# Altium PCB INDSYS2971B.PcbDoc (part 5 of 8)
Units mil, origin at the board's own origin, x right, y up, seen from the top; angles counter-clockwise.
Board outline 6450 x 5820 mil, 6 copper layers (Top Layer, Int1 (PGND), Int2 (AGND), Int3 (Signal), Int4 (PGND), Bottom Layer), stack 70.536 mil thick; 787 components, 431 nets, 2530 pads, 2497 vias.
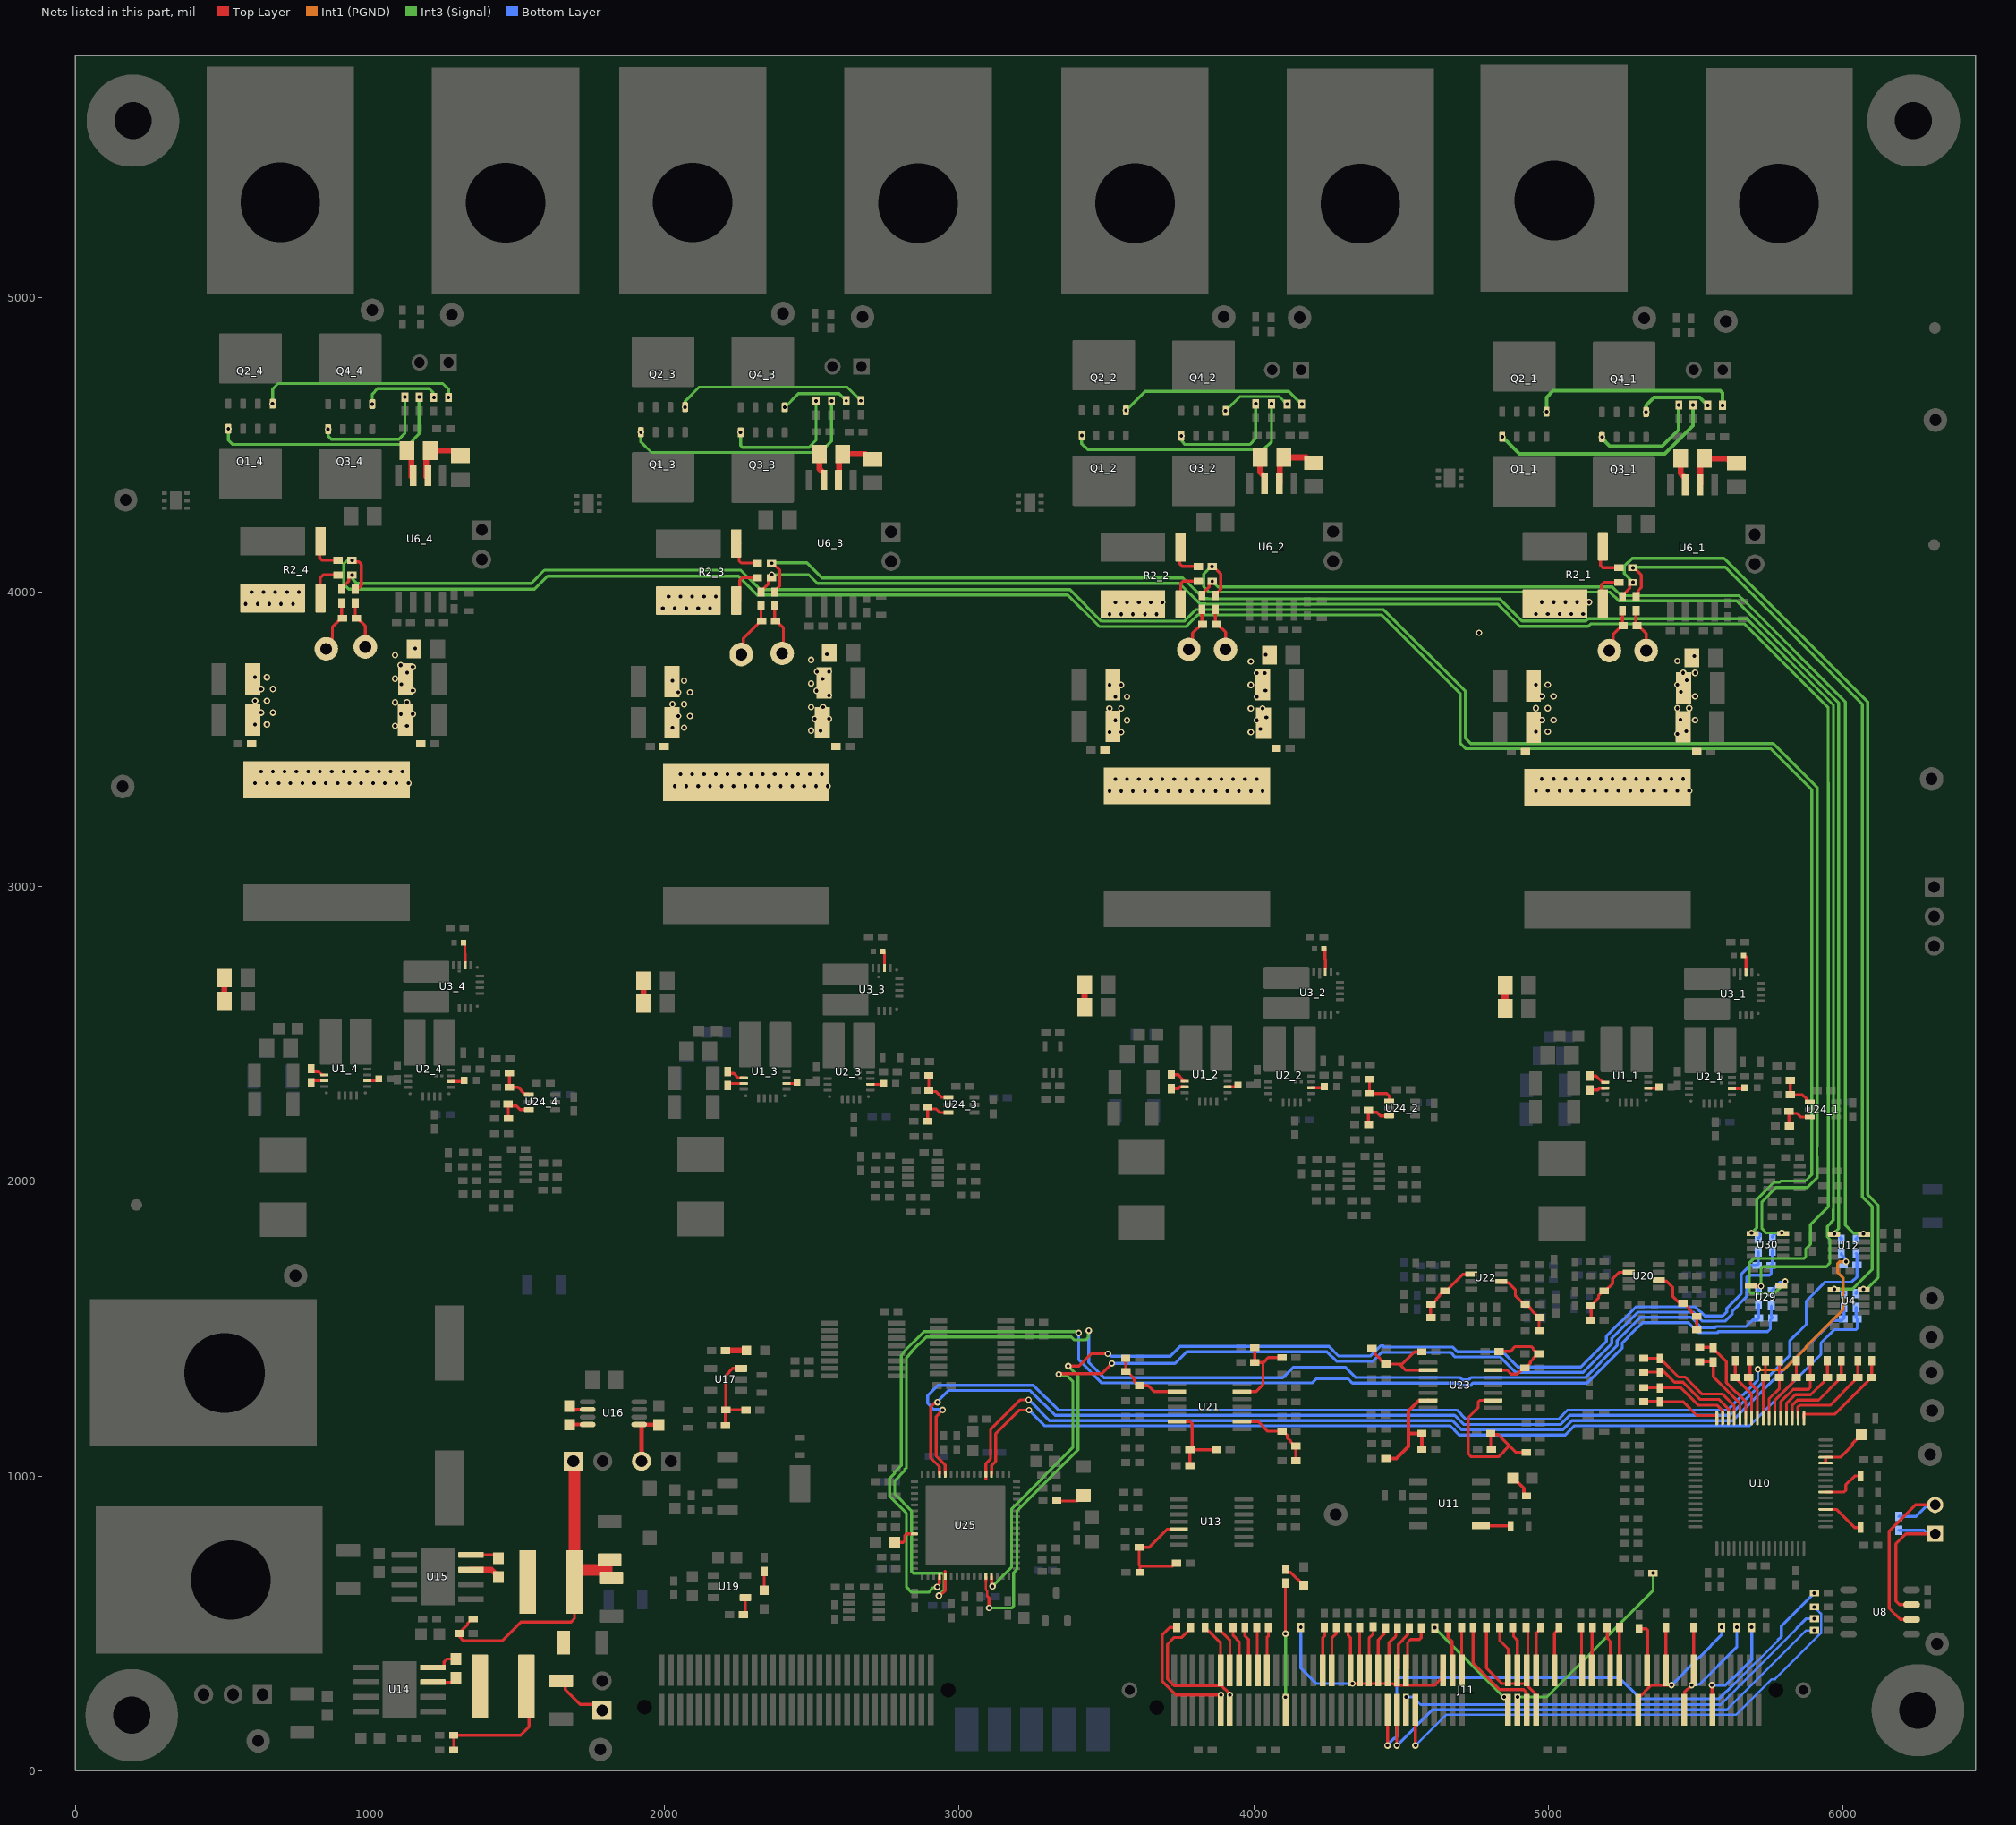
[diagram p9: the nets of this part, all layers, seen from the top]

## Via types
v1: diameter 22, hole 12.5, Top Layer to Bottom Layer, 873 vias
v2: diameter 22, hole 12, Top Layer to Bottom Layer, tented both sides, 788 vias
v3: diameter 22, hole 12, Top Layer to Bottom Layer, 586 vias
v4: diameter 22, hole 12.5, Top Layer to Bottom Layer, tented both sides, 249 vias
v5: diameter 24, hole 12, Top Layer to Bottom Layer, tented both sides, 1 vias

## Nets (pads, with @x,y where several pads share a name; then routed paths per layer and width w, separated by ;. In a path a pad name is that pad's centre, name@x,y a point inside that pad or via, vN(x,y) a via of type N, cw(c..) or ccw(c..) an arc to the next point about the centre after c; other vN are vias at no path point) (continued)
ISENA1: R4_1.1 R12_1.1 R210.1 U4.8 | length 3236.1
  Top Layer w10: R12_1.1@5252.12,3984.77 5252.12,3988.7 5276.41,4012.99 5276.41,4026.03 R4_1.1@5283.22,4032.84
  Int3 (Signal) w10: v2(5288.18,4033.35) 5258.39,4063.14 5258.39,4088.54 5285,4115.14 5596.3,4115.14 6084.34,3627.1 6084.34,1954.97 6117.15,1922.16 6120,1919.31 6120,1673.02 6083.45,1636.47 6072.3,1636.47 v2(6070,1634.17)
  Bottom Layer w10: R210.1@6045,1619.2 6045,1623.14 6051.81,1629.95 6062.53,1629.95 6066.75,1634.17 v2(6070,1634.17)
ISENA2: R4_2.1 R12_2.1 R211.1 U12.8 | length 4255
  Top Layer w10: R12_2.1@3824.12,3988.77 3824.12,3992.7 3848.41,4016.99 R4_2.1@3848.41,4030.03
  Int3 (Signal) w10: v2(3859.16,4036.84) 3859.32,4036.84 3878.14,4018.02 5217.13,4018.02 5247.13,3988.02 5647.4,3988.02 5665.28,3970.14 5666,3970.14 6008.59,3627.55 6008.59,1851.98 6036.18,1824.39 6067.7,1824.39 v2(6070,1822.09)
  Bottom Layer w10: R211.1@6045,1802.69 6045,1806.63 6058.17,1819.8 6067.7,1819.8 v2(6070,1822.09)
ISENA3: R4_3.1 R12_3.1 R212.1 U29.8 | length 6281.2
  Top Layer w10: R12_3.1@2327.51,4004.31 2351.8,4028.6 2351.8,4041.64 2358.61,4048.45 R4_3.1@2362.55,4048.45 2362.55,4058.64 v2(2363.38,4059.48) ; U29.8@5791.06,1644.83 5800.36,1644.83 5804.21,1648.69 v2(5804.21,1660.17)
  Int3 (Signal) w10: v2(2363.38,4059.48) 2489.37,4059.48 2518.71,4030.14 3747.54,4030.14 3817.54,3960.14 3837.44,3960.14 3838.19,3959.4 4828.48,3959.4 4903.48,3884.4 5135.68,3884.4 5143.56,3892.27 5667.32,3892.27 5950,3609.59 5950,3353.53 5950.43,3353.1 5950.43,2102.7 5950,2102.27 ; v2(5804.21,1660.17) 5804.21,1656.92 5798.21,1650.92 5798.21,1649.49 5768.91,1620.18 5687.52,1620.18 5681.66,1626.04 5681.66,1721.84 5698.37,1738.56 5868.49,1738.56 5874.35,1744.42 5874.35,1771.05 5890.23,1786.93 5890.23,1853.25 5950.43,1913.45 5950.43,2102.27
  Bottom Layer w10: R212.1@5757.14,1624.99 5757.14,1628.92 5786.09,1657.87 5801.92,1657.87 v2(5804.21,1660.17)
ISENA4: R4_4.1 R12_4.1 R213.1 U30.8 | length 7258.4
  Top Layer w10: R12_4.1@903.5,4009.77 903.5,4013.7 927.79,4037.99 927.79,4051.03 934.6,4057.84 v2(938.54,4057.84)
  Int3 (Signal) w10: v2(938.54,4057.84) 940.83,4055.55 940.83,4043.9 954.59,4030.14 1547.56,4030.14 1592.04,4074.62 2258.55,4074.62 2324.77,4008.41 3375.87,4008.41 3483.01,3901.27 3763.2,3901.27 3802.59,3940.66 4441.32,3940.66 4718.55,3663.44 4718.55,3504.12 4736.45,3486.22 5763.93,3486.22 5912.68,3337.46 5912.68,2118.34 5912.25,2117.91 5912.25,2086.64 5912.68,2086.21 5912.68,2012.27 5879.21,1978.8 5773.14,1978.8 5725.49,1931.14 5725.49,1839.34 5740,1824.83 v2(5792.78,1824.83)
  Bottom Layer w10: R213.1@5761.02,1810.42 5761.02,1814.12 5767.84,1820.93 5771.77,1820.93 5773.38,1822.53 5790.49,1822.53 v2(5792.78,1824.83)
ISENB1: R5_1.1 R13_1.1 R214.1 U4.1 | length 3221.9
  Top Layer w10: v2(5287.16,4082.84) 5291.1,4082.84 5315.78,4058.16 5315.78,4015.7 5304.81,4004.73 5304.81,3991.58 R13_1.1@5298,3984.77
  Int3 (Signal) w10: v2(5287.16,4082.84) 5288.45,4084.14 5602.03,4084.14 6066.47,3619.69 6066.47,1947.57 6099.28,1914.76 6099.28,1701.03 6032.42,1634.17 v2(5970.94,1634.17)
  Bottom Layer w10: v2(5970.94,1634.17) 5988.34,1634.17 5992.82,1629.69 5997.33,1629.69 6004.14,1622.88 R214.1@6004.14,1618.95
ISENB2: R5_2.1 R13_2.1 R215.1 U12.1 | length 4364.4
  Top Layer w10: v2(3858.08,4086.76) 3863.18,4086.76 3887.78,4062.16 3887.78,4010.48 3870,3992.7 R13_2.1@3870,3988.77
  Int3 (Signal) w10: v2(3858.08,4086.76) 3854.83,4086.76 3830,4061.92 3830,4018.14 3848,4000.14 5209.72,4000.14 5239.72,3970.14 5640,3970.14 5986.18,3623.97 5986.18,1840.13 5971.27,1825.22 v2(5971.27,1822.09)
  Bottom Layer w10: v2(5971.27,1822.09) 5973.56,1819.8 5981.83,1819.8 5995,1806.63 R215.1@5995,1802.69
ISENB3: R5_3.1 R13_3.1 R216.1 U29.1 | length 6188.8
  Top Layer w10: v2(2364.17,4098.25) 2366.69,4098.25 2391.17,4073.77 2391.17,4022.09 2373.39,4004.31 R13_3.1@2373.39,4000.37 ; U29.1@5688.7,1644.83 5689.08,1644.44 5721.43,1644.44 v2(5721.82,1644.06)
  Int3 (Signal) w10: v2(2364.17,4098.25) 2365.66,4099.74 2483.66,4099.74 2534.95,4048.45 3759.69,4048.45 3830.13,3978.02 3844.85,3978.02 3845.6,3977.27 4835.88,3977.27 4910.88,3902.27 5128.28,3902.27 5136.15,3910.14 5674.72,3910.14 5968.3,3616.56 5968.3,1906.05 5967.87,1905.62 5967.87,1867.74 5947.55,1847.42 5947.55,1832.14 5947.39,1831.98 5947.39,1811.81 5955.86,1803.35 5955.86,1722.16 5944.1,1710.4 5728.31,1710.4 5722.45,1704.54 5722.45,1644.69 v2(5721.82,1644.06)
  Bottom Layer w10: R216.1@5714.16,1629.2 5714.16,1633.15 5719.52,1638.52 5719.52,1641.76 v2(5721.82,1644.06)
ISENB4: R5_4.1 R13_4.1 R218.1 U30.1 | length 7383
  Top Layer w10: R5_4.1@942.47,4107.84 v2(938.54,4107.84) 943.89,4102.49 961.96,4102.49 969.77,4094.68 969.77,4021.54 958,4009.77 R13_4.1@949.38,4009.77 ; v2(5690,1824.83) 5692.14,1822.69 U30.1@5694.45,1822.69
  Int3 (Signal) w10: v2(938.54,4107.84) 938.07,4107.38 922.23,4107.38 909.77,4094.91 909.77,4027.87 927.5,4010.14 1558.54,4010.14 1602.42,4054.02 2251.22,4054.02 2314.7,3990.53 3368.47,3990.53 3475.6,3883.4 3770.6,3883.4 3809.99,3922.79 4433.92,3922.79 4700.68,3656.03 4700.68,3488.17 4720.51,3468.34 5756.52,3468.34 5894.81,3330.06 5894.81,2125.74 5894.38,2125.31 5894.38,2079.23 5894.81,2078.8 5894.81,2023.45 5872.61,2001.25 5789.46,2001.25 5784.87,1996.67 5765.74,1996.67 5707.61,1938.55 5707.61,1842.44 v2(5690,1824.83)
  Bottom Layer w10: v2(5690,1824.83) 5692.3,1822.53 5713.21,1822.53 5714.82,1820.93 5718.76,1820.93 5718.76,1813.53 R218.1@5713.15,1807.93
ISN1: C26.1 R214.2 U25.53 | length 3348.1
  Top Layer w10: 3090.43,990.14 U25.53@3090.43,1006.16 3090.43,1041.77 3106.3,1057.64 3106.3,1156.86 3208.07,1258.62 v2(3235.84,1258.62)
  Bottom Layer w10: v2(3235.84,1258.62) 3306.45,1188.02 4674.17,1188.02 4674.91,1187.28 4675.28,1187.28 4705.23,1157.33 5050.12,1157.33 5080.8,1188.02 5625.65,1188.02 5870.21,1432.58 5870.21,1432.72 5889.71,1452.21 5891.26,1452.21 5967.16,1528.11 5996.64,1528.11 6004.14,1535.61 R214.2@6004.14,1571.7
ISN2: C131.1 R215.2 U25.60 | length 3904.1
  Top Layer w10: v2(2943.76,1224.02) 2943.76,1223.77 2921.97,1201.97 2921.97,1068.41 2952.64,1037.74 U25.60@2952.64,1006.16
  Int1 (PGND) w10: v2(5711.7,1362.41) 5713.96,1360.14 5799.19,1360.14 5874.72,1435.67 5874.72,1438.64 6000.93,1564.85 6000.93,1672.79 5982.78,1690.94 5982.78,1721.39 5988.64,1727.25 v2(6010.77,1727.25)
  Bottom Layer w10: v2(2943.76,1224.02) 2941.47,1226.31 2913.5,1226.31 2892.77,1247.05 2892.77,1272.91 2927.87,1308.02 3252.13,1308.02 3336.38,1223.77 4689.35,1223.77 4720.04,1193.08 5035.31,1193.08 5066,1223.77 5608.96,1223.77 5711.7,1326.51 v2(5711.7,1362.41) ; R215.2@5995,1755.45 5995,1751.51 6008.48,1738.03 6008.48,1729.55 v2(6010.77,1727.25)
ISN3: C10.1 R216.2 U25.21 | length 4335.7
  Top Layer w10: v2(2931.36,593.7) 2934.61,593.7 2944.67,603.77 2946.54,603.77 2952.64,609.87 U25.21@2952.64,659.7 2952.64,676.14
  Int3 (Signal) w10: v2(2931.36,593.7) 2931.36,595.34 2949.07,613.05 2949.07,663.6 2942.39,670.27 2844.38,670.27 2838.52,676.13 2838.52,881.59 2781.75,938.37 2781.75,984.57 2814.65,1017.47 2814.65,1022.17 2821.12,1028.63 2821.12,1402.15 2837.14,1418.17 2837.14,1421.47 2887.94,1472.27 3380.57,1472.27 3391.11,1461.73 3429.61,1461.73 3437.7,1469.83 3437.7,1491.07 v2(3440,1493.36)
  Bottom Layer w10: v2(3440,1493.36) 3440,1385.42 3491.67,1333.75 4098.47,1333.75 4133.73,1369.02 4311.46,1369.02 4346.29,1334.19 4701.25,1334.19 4709.55,1325.89 4729.33,1325.89 4737.63,1334.19 5125.43,1334.19 5233.55,1442.31 5233.55,1459.56 5312.52,1538.53 5485.28,1538.53 5519.77,1504.04 5566.45,1504.04 5570.05,1507.64 5672.05,1507.64 5694.34,1529.93 5707.95,1529.93 C10.1@5714.76,1536.74 ; C10.1@5714.16,1541.69 R216.2@5714.16,1581.96
ISN4: C132.1 R218.2 U25.28 | length 3821.2
  Top Layer w8: 3090.43,644.78 3090.43,613.92 3095.43,608.92 3095.43,592.99
  Top Layer w10: 3090.43,644.78 U25.28@3090.43,659.7 ; 3095.43,592.99 3101.43,586.99 v2(3101.43,551.89) ; v2(3370,1373.17) 3406.34,1373.17 3447.91,1414.74 v2(3505,1414.74)
  Int3 (Signal) w10: v2(3101.43,551.89) 3178.19,551.89 3184.57,558.28 3184.57,671.56 3196.06,683.05 3196.06,880.82 3403.71,1088.47 3403.71,1339.45 v2(3370,1373.17)
  Bottom Layer w10: v2(3505,1414.74) 3508.25,1414.74 3516.6,1406.39 3716.7,1406.39 3750.21,1439.9 4255.52,1439.9 4288.26,1407.15 4396.05,1407.15 4430.82,1441.93 4439.11,1441.93 4443.51,1437.52 4676.02,1437.52 4691.52,1422.02 4844.85,1422.02 4896.93,1369.94 5110.63,1369.94 5197.8,1457.12 5197.8,1474.37 5297.71,1574.28 5500.09,1574.28 5530.98,1543.39 5592.62,1543.39 5606.23,1557 5606.23,1569.21 5655.15,1618.13 5655.15,1684.9 5685.07,1714.81 5708.53,1714.81 5713.15,1719.43 R218.2@5713.15,1760.68
ISP1: C26.2 R210.2 U25.52 | length 3381.7
  Top Layer w10: U25.52@3110.12,1006.16 3110.12,1036.18 3124.18,1050.24 3124.18,1143.2 3204.74,1223.76 v2(3236.94,1223.76) v2@3238.56,1223.76
  Bottom Layer w10: v2(3236.94,1223.76) 3290.56,1170.14 4666.55,1170.14 4667.29,1169.41 4667.87,1169.41 4681.86,1155.42 4681.86,1154.83 4697.24,1139.46 5057.52,1139.46 5088.21,1170.14 5682.7,1170.14 5925.75,1413.19 5925.75,1451.44 5971.1,1496.78 6043.08,1496.78 6048.94,1502.64 C26.2@6048.94,1533.16 6045,1537.1 R210.2@6045,1571.96
ISP2: C131.2 R211.2 U25.61 | length 3821.1
  Top Layer w10: v2(2926.51,1250.19) 2923.27,1250.19 2920.13,1247.05 2915.98,1247.05 2904.09,1235.17 2904.09,1061.01 2932.95,1032.15 U25.61@2932.95,1006.16
  Bottom Layer w10: v2(2926.51,1250.19) 2926.51,1253.44 2963.22,1290.14 3241.57,1290.14 3325.82,1205.89 4681.95,1205.89 4712.63,1175.21 5042.71,1175.21 5073.4,1205.89 5616.36,1205.89 5820.39,1409.93 5820.39,1459.07 5875.59,1514.27 5875.59,1593.94 5939.69,1658.05 6030.43,1658.05 6048.17,1675.79 C131.2@6048.17,1716.19 6048.17,1752.27 R211.2@6045,1755.45
ISP3: C10.2 R212.2 U25.20 | length 4314.6
  Top Layer w10: v2(2925.19,622.93) 2925.19,626.18 2932.95,633.94 U25.20@2932.95,659.7
  Int3 (Signal) w10: v2(2925.19,622.93) 2922.9,620.64 2911.56,620.64 2896.06,605.15 2839.14,605.15 2820.65,623.64 2820.65,874.19 2763.87,930.96 2763.87,991.98 2780.72,1008.82 2780.72,1013.51 2803.24,1036.04 2803.24,1409.55 2811.8,1418.11 2811.8,1421.41 2880.54,1490.14 3393.98,1490.14 3396.23,1487.9 3403.55,1487.9 v2(3405.84,1485.61)
  Bottom Layer w10: v2(3405.84,1485.61) 3405.84,1394.3 3484.27,1315.88 4198.3,1315.88 4212.57,1330.14 4320.17,1330.14 4335.3,1315.02 4695.15,1315.02 4702.15,1308.02 4736.73,1308.02 4743.73,1315.02 5131.54,1315.02 5251.43,1434.91 5251.43,1452.16 5285.63,1486.36 5319.93,1520.66 5474.79,1520.66 5509.28,1486.17 5573.85,1486.17 5577.45,1489.77 5744.75,1489.77 5754.13,1499.14 5754.13,1529.93 5760.94,1536.74 C10.2@5762.01,1536.74 5757.14,1541.61 R212.2@5757.14,1577.74
ISP4: C132.2 R213.2 U25.29 | length 3703.6
  Top Layer w10: U25.29@3110.12,659.7 3110.12,632.01 3113.31,628.82 v2(3113.31,625.57) ; v2(3338.15,1345.14) 3340.45,1347.44 3346.45,1347.44 3346.59,1347.58 3483.72,1347.58 v2(3518.39,1382.25)
  Int3 (Signal) w10: v2(3113.31,625.57) 3178.19,690.45 3178.19,888.54 3385.84,1096.19 3385.84,1321.22 3364.15,1342.91 3340.39,1342.91 v2(3338.15,1345.14)
  Bottom Layer w10: v2(3518.39,1382.25) 3732.65,1382.25 3772.42,1422.02 4248.12,1422.02 4280.86,1389.28 4404.41,1389.28 4434.78,1419.65 4668.62,1419.65 4684.12,1404.15 4837.45,1404.15 4889.53,1352.07 5118.03,1352.07 5215.68,1449.71 5215.68,1466.97 5305.12,1556.41 5492.69,1556.41 5523.57,1525.52 5600.03,1525.52 5624.1,1549.6 5624.1,1559.13 5674.57,1609.59 5674.57,1675.79 5680.43,1681.65 5751.23,1681.65 5757.09,1687.51 5757.09,1714.16 C132.2@5756.1,1715.14 5761.02,1720.07 R213.2@5761.02,1763.18
LED_BLINK: J11.96 R57.2 | length 430.5
  Top Layer w10: J11.96@4107.95,206.29 4108.07,206.4 4108.07,248.93 v2(4108.19,249.05) ; R57.2@4107.95,636.52 4107.82,636.39 4107.82,465.07 v2(4108.19,464.71)
  Int3 (Signal) w10: v2(4108.19,249.05) v2(4108.19,464.71)
NetC11_1_1: C11_1.1 C12_1.1 C13_1.2 C14_1.1 C15_1.1 C16_1.2 L1_1.2 R2_1.4 R7_1.2
  other v1: 4958.39,3326.14 4998.39,3326.14 5038.39,3326.14 5078.39,3326.14 5118.39,3326.14 5158.39,3326.14 5198.39,3326.14 5238.39,3326.14 5278.39,3326.14 5318.39,3326.14 5358.39,3326.14 5398.39,3326.14 5438.39,3326.14 5478.39,3326.14 4978.39,3366.14 5018.39,3366.14 5058.39,3366.14 5098.39,3366.14 5138.39,3366.14 5178.39,3366.14 5218.39,3366.14 5258.39,3366.14 5298.39,3366.14 5338.39,3366.14 5378.39,3366.14 5418.39,3366.14 5458.39,3366.14 5438.18,3518.53 4958.39,3526.14 4998.39,3526.14 5468.39,3527.57 4978.39,3566.14 5018.39,3566.14 5498.39,3566.14 5448.39,3567.57 4958.39,3606.14 4998.39,3606.14 5438.39,3606.14 5478.39,3606.14 4978.39,3646.14 5018.39,3646.14 5498.39,3646.14 5450.2,3661.52 4958.39,3686.14 4998.39,3686.14 5438.39,3686.14 5470.2,3701.52 5458.39,3726.14 5498.39,3726.14 5438.39,3766.14 5496.38,3783.18 4958.39,3926.14 4998.39,3926.14 5038.39,3926.14 5078.39,3926.14 5118.39,3926.14 4978.39,3966.14 5018.39,3966.14 5058.39,3966.14 5098.39,3966.14 5138.39,3966.14
  other v2: 4765,3861.64
NetC11_2_1: C11_2.1 C12_2.1 C13_2.2 C14_2.1 C15_2.1 C16_2.2 L1_2.2 R2_2.4 R7_2.2
  other v1: 3510,3325.14 3550,3325.14 3590,3325.14 3630,3325.14 3670,3325.14 3710,3325.14 3750,3325.14 3790,3325.14 3830,3325.14 3870,3325.14 3910,3325.14 3950,3325.14 3990,3325.14 4030,3325.14 3530,3365.14 3570,3365.14 3610,3365.14 3650,3365.14 3690,3365.14 3730,3365.14 3770,3365.14 3810,3365.14 3850,3365.14 3890,3365.14 3930,3365.14 3970,3365.14 4010,3365.14 3510,3525.14 3550,3525.14 3990,3525.14 4023.03,3535.18 3530,3565.14 3570,3565.14 4010,3565.14 4043.03,3575.18 3510,3605.14 3550,3605.14 3990,3605.14 4030,3605.14 3530,3645.14 3570,3645.14 4010,3645.14 4040,3666.14 3510,3685.14 3550,3685.14 3990,3685.14 4010,3725.14 4037.52,3725.18 3990,3765.14 4041.1,3787.35 3510,3925.14 3550,3925.14 3590,3925.14 3630,3925.14 3670,3925.14 3530,3965.14 3570,3965.14 3610,3965.14 3650,3965.14 3690,3965.14
NetC11_3_1: C11_3.1 C12_3.1 C13_3.2 C14_3.1 C15_3.1 C16_3.2 L1_3.2 R2_3.4 R7_3.2
  other v1: 2033.78,3341.75 2073.78,3341.75 2113.78,3341.75 2153.78,3341.75 2193.78,3341.75 2233.78,3341.75 2273.78,3341.75 2313.78,3341.75 2353.78,3341.75 2393.78,3341.75 2433.78,3341.75 2473.78,3341.75 2513.78,3341.75 2553.78,3341.75 2053.78,3381.75 2093.78,3381.75 2133.78,3381.75 2173.78,3381.75 2213.78,3381.75 2253.78,3381.75 2293.78,3381.75 2333.78,3381.75 2373.78,3381.75 2413.78,3381.75 2453.78,3381.75 2493.78,3381.75 2533.78,3381.75 2497.64,3529.86 2529.45,3529.86 2026.17,3539.71 2066.17,3539.71 2509.45,3569.86 2557.64,3569.86 2046.17,3579.71 2086.17,3579.71 2497.64,3609.86 2537.64,3609.86 2026.17,3619.71 2066.17,3619.71 2557.64,3649.86 2046.17,3659.71 2086.17,3659.71 2516.18,3665.24 2497.64,3689.86 2026.17,3699.71 2066.17,3699.71 2536.18,3705.24 2517.64,3729.86 2557.64,3729.86 2497.64,3769.86 2551.18,3788.81 1993.78,3945.34 2033.78,3945.34 2073.78,3945.34 2113.78,3945.34 2153.78,3945.34 2013.78,3985.34 2053.78,3985.34 2093.78,3985.34 2133.78,3985.34 2173.78,3985.34
NetC11_4_1: C11_4.1 C12_4.1 C13_4.2 C14_4.1 C15_4.1 C16_4.2 L1_4.2 R2_4.4 R7_4.2
  other v1: 609.77,3351.14 649.77,3351.14 689.77,3351.14 729.77,3351.14 769.77,3351.14 809.77,3351.14 849.77,3351.14 889.77,3351.14 929.77,3351.14 969.77,3351.14 1009.77,3351.14 1049.77,3351.14 1089.77,3351.14 1129.77,3351.14 629.77,3391.14 669.77,3391.14 709.77,3391.14 749.77,3391.14 789.77,3391.14 829.77,3391.14 869.77,3391.14 909.77,3391.14 949.77,3391.14 989.77,3391.14 1029.77,3391.14 1069.77,3391.14 1109.77,3391.14 1084.85,3546.11 1124.85,3546.11 609.77,3551.14 649.77,3551.14 1104.85,3586.11 1144.85,3586.11 629.77,3591.14 669.77,3591.14 1084.85,3626.11 1124.85,3626.11 609.77,3631.14 649.77,3631.14 1144.85,3666.11 629.77,3671.14 669.77,3671.14 1105.85,3687.07 1084.85,3706.11 609.77,3711.14 649.77,3711.14 1125.85,3727.07 1144.85,3746.11 1103.82,3751.69 1084.85,3786.11 1153.47,3808.49 578,3959.99 618,3959.99 658,3959.99 698,3959.99 738,3959.99 598,3999.99 638,3999.99 678,3999.99 718,3999.99 758,3999.99
NetC17_1_1: C17_1.1 U1_1.8 | length 60.5
  Top Layer w10: C17_1.1@5141.79,2357.79 5163.16,2357.79 5184.65,2336.3 U1_1.8@5193.35,2336.3
NetC17_1_2: C17_1.2 U1_1.9 | length 54.1
  Top Layer w10: C17_1.2@5141.79,2310.55 5168.6,2310.55 5174.59,2316.53 5193.28,2316.53 U1_1.9@5193.35,2316.61
NetC17_2_1: C17_2.1 U1_2.8 | length 59.2
  Top Layer w10: C17_2.1@3720.27,2362.1 3743.55,2362.1 3756.58,2349.07 3756.58,2340.38 3756.65,2340.3 U1_2.8@3765.36,2340.3
NetC17_2_2: C17_2.2 U1_2.9 | length 47.5
  Top Layer w10: C17_2.2@3720.27,2314.86 3743.53,2314.86 3749.21,2320.53 3765.27,2320.53 U1_2.9@3765.36,2320.61
NetC17_3_1: C17_3.1 U1_3.8 | length 63.6
  Top Layer w10: C17_3.1@2213.78,2372.81 2219.76,2366.83 2234.74,2366.83 2249.66,2351.91 U1_3.8@2268.75,2351.91
NetC17_3_2: C17_3.2 U1_3.9 | length 57.7
  Top Layer w10: C17_3.2@2213.78,2325.56 2220.44,2332.22 U1_3.9@2268.75,2332.22
NetC17_4_1: C17_4.1 U1_4.8 | length 55.9
  Top Layer w10: C17_4.1@800,2382.58 800,2378.64 806.81,2371.83 825.5,2371.83 836.03,2361.3 U1_4.8@844.73,2361.3
NetC17_4_2: C17_4.2 U1_4.9 | length 47.3
  Top Layer w10: C17_4.2@800,2335.34 806.28,2341.61 U1_4.9@844.73,2341.61
NetC18_1_1: C18_1.1 R3_1.1 | length 77.4
  Top Layer w25: C18_1.1@4853.62,2587.64 R3_1.1@4853.62,2665.08
NetC18_2_1: C18_2.1 R3_2.1 | length 77.4
  Top Layer w20: C18_2.1@3425.62,2591.64 R3_2.1@3425.62,2669.08
NetC18_3_1: C18_3.1 R3_3.1 | length 77.4
  Top Layer w20: C18_3.1@1929.01,2603.25 R3_3.1@1929.01,2680.68
NetC18_4_1: C18_4.1 R3_4.1 | length 77.4
  Top Layer w20: C18_4.1@505,2612.64 R3_4.1@505,2690.08
NetC21_1_1: C21_1.1 R13_1.2 TP4_1.1 | length 152.4
  Top Layer w10: R13_1.2@5298,3937.52 5298,3890.22 C21_1.1@5301.62,3886.6 5305.56,3886.6 5332.36,3859.8 TP4_1.1@5332.36,3801.64
NetC21_1_2: C21_1.2 R12_1.2 TP3_1.1 | length 158.5
  Top Layer w10: TP3_1.1@5207.68,3801.64 5220.49,3814.45 5220.49,3856.64 5250.44,3886.6 C21_1.2@5254.38,3886.6 5252.12,3888.86 R12_1.2@5252.12,3937.52
NetC21_2_1: C21_2.1 R13_2.2 TP4_2.1 | length 152.4
  Top Layer w10: R13_2.2@3870,3941.52 3870,3894.22 C21_2.1@3873.62,3890.6 3877.56,3890.6 3904.36,3863.8 TP4_2.1@3904.36,3805.64
NetC21_2_2: C21_2.2 R12_2.2 TP3_2.1 | length 158.5
  Top Layer w10: TP3_2.1@3779.68,3805.64 3792.49,3818.45 3792.49,3860.64 3822.44,3890.6 C21_2.2@3826.38,3890.6 3824.12,3892.86 R12_2.2@3824.12,3941.52
NetC21_3_1: C21_3.1 R13_3.2 TP4_3.1 | length 182.9
  Top Layer w10: R13_3.2@2373.39,3953.13 2373.39,3905.83 2377.33,3905.83 2403.06,3880.1 2403.06,3796.04 TP4_3.1@2399.09,3792.07 TP4_3.1@2395.13,3788.11
NetC21_3_2: C21_3.2 R12_3.2 TP3_3.1 | length 189.7
  Top Layer w10: TP3_3.1@2260.21,3788.34 2266.96,3795.09 2266.96,3843.34 C21_3.2@2325.83,3902.21 ; C21_3.2@2327.51,3904.46 R12_3.2@2327.51,3953.13
NetC21_4_1: C21_4.1 R13_4.2 TP4_4.1 | length 171.5
  Top Layer w10: R13_4.2@949.38,3962.52 949.38,3915.22 C21_4.1@953,3911.6 956.94,3911.6 983.74,3884.8 TP4_4.1@983.74,3807.53
NetC21_4_2: C21_4.2 R12_4.2 TP3_4.1 | length 180.8
  Top Layer w10: TP3_4.1@851.24,3807.53 851.24,3818.83 871.86,3839.45 871.86,3881.64 901.82,3911.6 C21_4.2@905.76,3911.6 903.5,3913.86 R12_4.2@903.5,3962.52
NetC32_1_1: C32_1.1 U6_1.7 | length 95.8
  Top Layer w20: C32_1.1@5449.57,4453.49 5449.57,4403.12 5465,4387.69 U6_1.7@5465,4364.07
NetC32_1_2: C32_1.2 C34_1.1 U6_1.6 | length 204.8
  Top Layer w20: U6_1.6@5515,4364.07 5516.81,4365.88 5516.81,4440.73 C32_1.2@5529.57,4453.49 5606.48,4453.49 5624.8,4435.17 C34_1.1@5631.3,4435.17
NetC32_2_1: C32_2.1 U6_2.7 | length 95.8
  Top Layer w20: C32_2.1@4021.57,4457.49 4021.57,4407.12 4037,4391.69 U6_2.7@4037,4368.07
NetC32_2_2: C32_2.2 C34_2.1 U6_2.6 | length 204.8
  Top Layer w20: U6_2.6@4087,4368.07 4088.81,4369.88 4088.81,4444.73 C32_2.2@4101.57,4457.49 4178.48,4457.49 4196.8,4439.17 C34_2.1@4203.3,4439.17
NetC32_3_1: C32_3.1 U6_3.7 | length 95.8
  Top Layer w20: C32_3.1@2524.97,4469.1 2524.97,4418.73 2540.39,4403.3 U6_3.7@2540.39,4379.68
NetC32_3_2: C32_3.2 C34_3.1 U6_3.6 | length 204.8
  Top Layer w20: U6_3.6@2590.39,4379.68 2592.2,4381.49 2592.2,4456.34 C32_3.2@2604.97,4469.1 2681.87,4469.1 2700.19,4450.78 C34_3.1@2706.69,4450.78
NetC32_4_1: C32_4.1 U6_4.7 | length 95.8
  Top Layer w20: C32_4.1@1124.57,4480.43 1124.57,4473.93 1140,4458.51 U6_4.7@1140,4391.01
NetC32_4_2: C32_4.2 C34_4.1 U6_4.6 | length 204.8
  Top Layer w20: U6_4.6@1190,4391.01 1190,4465.86 C32_4.2@1204.57,4480.43 1281.48,4480.43 1299.8,4462.11 C34_4.1@1306.3,4462.11
NetC42_1: C42.1 R78.2 U10.49 | length 354.3
  Top Layer w10: U10.49@5867.64,1196.6 5867.64,1210.07 5867.72,1210.14 5973.86,1210.14 6087.52,1323.81 6087.52,1327.74 6094.33,1334.56 C42.1@6098.27,1334.56 R78.2@6098.27,1390.93
NetC42_2: C42.2 R81.2 U10.50 | length 341
  Top Layer w10: U10.50@5847.95,1196.6 5847.95,1234.29 5853.81,1240.14 5956.61,1240.14 6040.28,1323.81 6040.28,1327.74 6047.09,1334.56 C42.2@6051.02,1334.56 R81.2@6051.02,1390.93
NetC48_1: C48.1 R83.2 U10.51 | length 307.6
  Top Layer w10: U10.51@5828.27,1196.6 5828.27,1239.88 5846.41,1258.02 5918.11,1258.02 5983.9,1323.81 5983.9,1327.74 5990.71,1334.56 C48.1@5994.65,1334.56 R83.2@5994.65,1390.93
NetC48_2: C48.2 R85.2 U10.52 | length 284.5
  Top Layer w10: U10.52@5808.58,1196.6 5808.58,1245.47 5839,1275.89 5890.84,1275.89 5936.65,1321.71 5936.65,1327.74 5943.46,1334.56 C48.2@5947.4,1334.56 R85.2@5947.4,1390.93
NetC49_1: C49.1 R86.2 U10.53 | length 266.3
  Top Layer w10: U10.53@5788.9,1196.6 5788.9,1251.06 5831.6,1293.77 5883.43,1293.77 5889.29,1299.62 C49.1@5889.29,1334.56 R86.2@5889.29,1390.93
NetC49_2: C49.2 R87.2 U10.54 | length 226.8
  Top Layer w10: U10.54@5769.21,1196.6 5769.21,1256.66 5831.3,1318.74 5831.3,1327.74 5838.11,1334.56 C49.2@5842.05,1334.56 R87.2@5842.05,1390.93
NetC50_1: C50.1 R90.2 U10.55 | length 208.9
  Top Layer w10: U10.55@5749.53,1196.6 5749.53,1262.25 5784.65,1297.37 C50.1@5784.65,1334.56 R90.2@5784.65,1390.93
NetC50_2: C50.2 R91.2 U10.56 | length 197.9
  Top Layer w10: U10.56@5729.84,1196.6 5729.84,1327.74 5736.65,1334.56 C50.2@5737.4,1334.56 R91.2@5737.4,1390.93
NetC51_1: C51.1 R93.2 U10.57 | length 208.7
  Top Layer w10: R93.2@5684.8,1390.93 5684.8,1339.16 C51.1@5680.2,1334.56 5686.54,1328.21 5686.54,1313.6 5710.16,1289.99 U10.57@5710.16,1196.6
NetC51_2: C51.2 R94.2 U10.58 | length 221.2
  Top Layer w10: R94.2@5634.8,1390.93 5634.8,1336.41 C51.2@5632.95,1334.56 5636.89,1334.56 5643.7,1327.74 5643.7,1323.81 5690.47,1277.04 U10.58@5690.47,1196.6
NetC52_1: C52.1 R95.2 U10.59 | length 331.8
  Top Layer w10: R95.2@5514.21,1436.92 5553.19,1436.92 5555,1438.73 C52.1@5555,1440.14 ; C52.1@5565,1440.14 5565,1424.83 5566.81,1423.02 5569.27,1423.02 5604.33,1387.96 5604.33,1317.41 5670.79,1250.96 U10.59@5670.79,1196.6
NetC52_2: C52.2 R96.2 U10.60 | length 273.6
  Top Layer w10: R96.2@5514.21,1387.55 5557.4,1387.55 C52.2@5560,1386.52 5560,1336.47 5651.1,1245.36 U10.60@5651.1,1196.6
NetC53_1: C53.1 R97.2 U10.61 | length 419.2
  Top Layer w10: R97.2@5324.21,1399.91 5379.76,1399.91 5380,1400.14 C53.1@5380,1398.77 5380,1394.83 5386.81,1388.02 5389.6,1388.02 5441.73,1335.89 5464.81,1335.89 5522.68,1278.02 5591.85,1278.02 5631.34,1238.53 5631.34,1196.68 U10.61@5631.42,1196.6
NetC53_2: C53.2 R98.2 U10.62 | length 377.3
  Top Layer w10: R98.2@5324.21,1352.66 5380.95,1352.66 5386.81,1358.52 5386.81,1360.14 5428.94,1318.02 5457.4,1318.02 5515.28,1260.14 5578.95,1260.14 5611.65,1227.44 U10.62@5611.73,1196.6 U10.62@5611.73,1196.6
NetC54_1: C54.1 R100.2 U10.63 | length 320.8
  Top Layer w10: R100.2@5330,1300.14 5330.12,1300.03 5378.74,1300.03 C54.1@5380,1298.77 5381.38,1300.14 5450,1300.14 5510,1240.14 5573.67,1240.14 5591.97,1221.85 U10.63@5592.05,1196.6 U10.63@5592.05,1196.6
NetC54_2: C54.2 R102.2 U10.64 | length 278.3
  Top Layer w10: R102.2@5324.21,1252.78 5377.36,1252.78 5380,1250.14 C54.2@5380,1251.52 5458.62,1251.52 5505,1205.14 5572.28,1205.14 5572.36,1205.07 U10.64@5572.36,1196.6
NetC57_1: C57.1 U10.36 | length 144
  Top Layer w10: U10.36@5941.46,886.56 5978.58,886.56 6040,825.14 C57.1@6060,825.14
NetC58_1: C58.1 U10.39 | length 151.9
  Top Layer w10: U10.39@5941.46,945.62 5941.54,945.7 6004.14,945.7 6010,951.55 6010,969.99 6040.16,1000.14 C58.1@6060,1000.14
NetC59_1: C59.1 U10.44 U10.45 | length 176.8
  Top Layer w10: U10.44@5941.46,1044.04 U10.45@5941.46,1063.73 5991.93,1063.73 6032.59,1104.39 6032.59,1110.21 6062.52,1140.14 C59.1@6063.5,1140.14
NetC61_1: C61.1 U11.5 | length 102.5
  Top Layer w10: U11.5@4770.75,830.69 4871.51,830.69 C61.1@4872.71,829.49
NetC63_1: C63.1 R107.1 | length 81.6
  Top Layer w12: C63.1@4881.22,992.76 4882.2,992.76 4916.59,958.37 4916.59,938.57 4922.4,932.76 R107.1@4926.34,932.76
NetC70_1: C70.1 R115.1 R116.1 U13.5 | length 374
  Top Layer w10: R116.1@3613.72,673.02 3613.72,694.19 ; C70.1@3737.99,704.02 3734.05,704.02 3724.23,694.19 3613.72,694.19 ; U13.5@3745.47,818.43 3705.52,818.43 3645.32,758.23 R115.1@3611.06,758.23 3611.06,696.84 3613.72,694.19
NetC72_1: C72.1 U14.7 | length 89
  Top Layer w10: U14.7@1213.19,300.1 1279.94,300.1 1295,315.16 C72.1@1295,316.15
NetC72_2: C72.2 L2.1 U14.8 | length 102.3
  Top Layer w10: U14.8@1213.19,350.1 1217.79,350.1 1222.63,354.95 1251.5,354.95 1251.5,369.34 1261.3,379.14 C72.2@1295,379.14
NetC73_1: C73.1 U15.7 | length 103.8
  Top Layer w20: U15.7@1342.7,682.07 1412.13,682.07 1435.75,658.45 C73.1@1435.75,657.47
NetC73_2: C73.2 L3.1 U15.8 | length 97.9
  Top Layer w10: U15.8@1342.7,732.07 1424.13,732.07 C73.2@1435.75,720.46
NetC74_2: C74.2 C75.2 J14.1 L2.2 R118.2 R120.2 | length 643.5
  Top Layer w10: R118.2@1283.62,70.14 R120.2@1283.62,120.14 1510.55,120.14 1539.53,149.12 L2.2@1539.53,285.14 ; C74.2@1648.47,304.87 1663.04,290.29 1663.04,275.1 1713.04,225.1 1767.24,225.1 J14.1@1787.64,204.71
NetC76_2: C76.2 C77.2 J15.1 L3.2 R119.2 R121.2 | length 1205.1
  Top Layer w10: R121.2@1302.19,465.25 R121.2@1304.16,463.29 ; R121.2@1304.16,453.44 1317.03,440.57 1448.72,440.57 1512.5,504.35 1682.22,504.35 1693.89,516.02 L3.2@1693.89,640.37 ; R121.2@1305.22,465.25 1312.03,472.07 1312.03,477.07 1330.81,495.85 1330.81,500.05 1345.5,514.74 R119.2@1349.43,514.74
  Top Layer w40: J15.1@1690,1050.25 1693.89,1046.36 L3.2@1693.89,640.37 ; L3.2@1693.89,672.65 1702.04,680.8 1803.54,680.8 ; C77.2@1803.54,652.27 1803.54,680.8 ; C76.2@1803.54,709.33 1803.54,680.8
NetC82_1: C82.1 U16.4 | length 61.6
  Top Layer w12: C82.1@1677.17,1174.14 1677.65,1174.63 U16.4@1738.62,1174.63
NetC82_2: C82.2 U16.2 | length 66.1
  Top Layer w12: C82.2@1677.17,1237.14 1688.49,1225.81 U16.2@1738.62,1225.81
NetC88_1: C88.1 J17.2 U16.5 | length 190.8
  Top Layer w15: U16.5@1913.81,1174.63 1920.2,1174.63 U16.5@1920.69,1174.14 ; J17.2@1921.46,1050.23 1921.46,1173.37 U16.5@1920.69,1174.14 ; C88.1@1980,1173.65 1979.51,1174.14 U16.5@1920.69,1174.14
NetC90_2: C90.2 R127.1 R128.2 U17.3 | length 303.4
  Top Layer w10: C90.2@2207.62,1172.83 C90.2@2206.21,1171.42 2206.21,1222.92 R128.2@2207.62,1224.34 ; U17.3@2258.8,1365.17 2258.57,1365.41 2231.09,1365.41 2207.62,1341.94 R128.2@2207.62,1224.34 ; R127.1@2276.55,1223.45 2272.62,1223.45 2272.17,1223.89 2208.07,1223.89 R128.2@2207.62,1224.34
NetC95_1: C95.1 U19.4 | length 60.6
  Top Layer w10: C95.1@2267.55,529.48 2274.31,536.24 U19.4@2274.31,587.31
NetC97_1: C97.1 R136.2 R141.2 U20.2 | length 247.6
  Top Layer w10: U20.2@5375.58,1665.64 5379.43,1661.78 5400.44,1661.78 5423.26,1638.96 5423.26,1608.68 5446.69,1585.25 5454.56,1585.25 5456.1,1586.78 R136.2@5457.3,1586.78 5461.23,1586.78 5475.92,1572.1 5475.92,1568.93 5485.92,1558.93 5485.92,1556.47 5500.6,1541.78 R141.2@5504.54,1541.78 C97.1@5504.54,1496.78
NetC100_1: C100.1 R142.2 R143.1 U21.2 | length 252.6
  Top Layer w10: C100.1@3565.32,1399.93 3565.32,1356.21 R143.1@3566.38,1355.14 3570.32,1355.14 3585,1340.46 3585,1338 3593.94,1329.06 3593.94,1321.39 3608.62,1306.7 R142.2@3612.56,1306.7 3641.38,1306.7 3661.38,1286.7 U21.2@3739.49,1286.7
NetC101_1: C101.1 R147.2 R150.2 U20.6 | length 239.3
  Top Layer w10: C101.1@5142.44,1528.44 5145.92,1526.78 5145.92,1574.96 R150.2@5142.44,1578.44 ; R150.2@5150.92,1581.78 5150.92,1582.98 5161.06,1593.12 5161.06,1595.58 5171.06,1605.58 5171.06,1613.75 5185.74,1628.44 R147.2@5189.68,1628.44 ; R147.2@5191.97,1626.78 5218.3,1653.12 5218.3,1669.17 5240.37,1691.23 U20.6@5273.21,1691.23
NetC102_1: C102.1 R153.2 R154.1 U21.6 | length 289.3
  Top Layer w10: U21.6@3739.49,1184.34 3739.81,1184.02 3785.28,1184.02 3791.14,1178.17 3791.14,1095.96 R154.1@3784.33,1089.14 ; C102.1@3783.35,1035.52 R154.1@3783.35,1089.14 R154.1@3784.33,1089.14 ; R153.2@3872.95,1089.14 R154.1@3784.33,1089.14
NetC103_1: C103.1 R159.2 R164.2 U22.2 | length 241.4
  Top Layer w10: U22.2@4840.54,1660.17 4844.4,1656.31 4865.4,1656.31 4888.23,1633.48 4888.23,1612.76 4917.87,1583.12 4925.74,1583.12 4932.55,1576.31 4940.43,1568.44 4940.43,1565.27 4953.46,1552.23 4958.3,1547.39 4958.3,1544.93 4965.11,1538.12 C103.1@4969.05,1538.12 4969.05,1494.5 4970.43,1493.12 R164.2@4969.05,1493.12
NetC106_1: C106.1 R163.2 R165.1 U21.9 | length 273.8
  Top Layer w10: U21.9@3959.96,1184.34 4015.32,1184.34 4047.84,1151.83 R163.2@4096.1,1151.83 4100.04,1151.83 4114.73,1137.14 4114.73,1128.97 4124.73,1118.97 4124.73,1116.51 4139.41,1101.83 R165.1@4143.35,1101.83 C106.1@4143.35,1051.83
NetC107_1: C107.1 R171.2 R176.1 U21.13 | length 307.6
  Top Layer w10: U21.13@3959.96,1286.7 4008.27,1286.7 4031.46,1309.89 4031.46,1382.25 4028.19,1385.52 ; R176.1@4003.35,1435.52 C107.1@4003.35,1385.52 4028.19,1385.52 ; R171.2@4096.1,1401.83 4049.73,1401.83 4033.43,1385.52 4028.19,1385.52
NetC108_1: C108.1 R172.2 R174.2 U22.6 | length 220.9
  Top Layer w10: R174.2@4601.8,1538.12 4600.43,1538.12 4600.43,1581.74 C108.1@4601.8,1583.12 4605.74,1583.12 4620.43,1597.81 4620.43,1600.98 4630.43,1610.98 4630.43,1614.92 4636.82,1621.31 4648.61,1621.31 R172.2@4650.43,1623.12 ; R172.2@4655.43,1633.12 4657.99,1633.12 4709.6,1684.74 4737.16,1684.74 U22.6@4738.18,1685.76
NetC110_2: C110.2 R182.2 R183.2 U23.6 | length 396.1
  Top Layer w12: R182.2@4448.07,1059.72 4484.57,1059.72 4525.25,1100.4 4525.25,1144.44 ; C110.2@4570.75,1090.43 R183.2@4570.75,1144.44 4525.25,1144.44 ; U23.6@4592.31,1256.84 4591.42,1255.95 4560.18,1255.95 4525.25,1221.02 4525.25,1144.44
NetC111_2: C111.2 R181.2 R184.2 U23.2 | length 323.2
  Top Layer w10: C111.2@4401.06,1433.66 4405,1433.66 4411.81,1426.85 4411.81,1414.74 4429.69,1396.86 4429.69,1394.4 4444.37,1379.72 R181.2@4448.31,1379.72 4495.56,1379.72 ; R184.2@4570.75,1421.56 4545.16,1421.56 4503.32,1379.72 4495.56,1379.72 ; U23.2@4592.31,1359.2 4516.07,1359.2 4495.56,1379.72
NetC112_2: C112.2 R190.2 R191.2 U23.13 | length 343.6
  Top Layer w10: U23.13@4812.79,1359.2 4860.96,1359.2 4874.02,1346.15 4895.7,1346.15 4916.65,1367.1 4924.53,1367.1 4939.21,1381.79 4939.21,1387.59 4949.21,1397.59 4949.21,1400.05 R191.2@4963.9,1414.74 ; C112.2@4832.5,1422.91 4871.71,1422.91 4888.22,1439.42 4941.67,1439.42 4949.21,1431.88 4949.21,1429.42 R191.2@4963.9,1414.74 ; R191.2@4967.83,1414.74 R191.2@4963.9,1414.74
NetC113_2: C113.2 R189.2 R192.2 U23.9 | length 603.9
  Top Layer w10: C113.2@4806.97,1090.43 4804.69,1092.71 R192.2@4804.69,1144.44 4808.16,1140.97 4829.58,1140.97 4863.45,1107.1 4867.93,1102.61 ; U23.9@4812.79,1256.84 4767.91,1256.84 4762.06,1250.98 4762.06,1231.82 4728.82,1198.58 4728.82,1075.57 4738.99,1065.4 4830.71,1065.4 4867.93,1102.61 ; R189.2@4925.71,1079.72 4890.82,1079.72 4867.93,1102.61
NetC122_2: C122.2 U25.10 | length 91.2
  Top Layer w10: C122.2@2779.4,774.29 2810.2,774.29 2816.06,780.14 2816.06,797.55 2821.92,803.4 U25.10@2848.31,803.4
NetD1_2: D1.2 R57.1 | length 87.2
  Top Layer w10: R57.1@4107.95,683.77 4107.95,679.83 4114.76,673.02 4125.63,673.02 D1.2@4170,628.65
NetD2_2: D2.2 R126.1 | length 70.9
  Top Layer w20: R126.1@2206.74,1425.82 D2.2@2277.6,1425.82
NetD3_2: D3.2 R131.1 | length 63.8
  Top Layer w10: D3.2@2338.06,611.83 R131.1@2338.06,675.65
NetD4_1_2: D4_1.2 R15_1.1 U24_1.6 | length 127.9
  Top Layer w10: R15_1.1@5818.1,2188.29 5817.37,2189.01 D4_1.2@5817.37,2237.28 5824.18,2230.47 5845.8,2230.47 5857.95,2218.32 U24_1.6@5888.1,2218.32
NetD4_2_2: D4_2.2 R15_2.1 U24_2.6 | length 127.9
  Top Layer w10: R15_2.1@4390.1,2192.29 4389.37,2193.01 D4_2.2@4389.37,2241.28 4396.18,2234.47 4417.8,2234.47 4429.95,2222.32 U24_2.6@4460.1,2222.32
NetD4_3_2: D4_3.2 R15_3.1 U24_3.6 | length 127.9
  Top Layer w10: R15_3.1@2893.49,2203.89 2892.76,2204.62 D4_3.2@2892.76,2252.89 2899.57,2246.08 2921.19,2246.08 2933.34,2233.93 U24_3.6@2963.49,2233.93
NetD4_4_2: D4_4.2 R15_4.1 U24_4.6 | length 127.9
  Top Layer w10: R15_4.1@1469.48,2213.29 1468.75,2214.01 D4_4.2@1468.75,2262.28 1475.56,2255.47 1497.18,2255.47 1509.33,2243.32 U24_4.6@1539.48,2243.32
NetD5_1_2: D5_1.2 R193_1.1 U24_1.4 | length 130.7
  Top Layer w10: R193_1.1@5821.31,2342.84 5821.31,2294.48 D5_1.2@5821.58,2294.21 5863.4,2294.21 5876.37,2281.24 5876.37,2272.38 5879.24,2269.5 U24_1.4@5888.1,2269.5
NetD5_2_2: D5_2.2 R193_2.1 U24_2.4 | length 135.4
  Top Layer w10: R193_2.1@4393.31,2346.84 4393.31,2298.48 D5_2.2@4393.58,2298.21 4452.25,2298.21 4459.94,2290.52 4459.94,2273.66 U24_2.4@4460.1,2273.51
NetD5_3_2: D5_3.2 R193_3.1 U24_3.4 | length 129.4
  Top Layer w10: R193_3.1@2896.7,2358.45 2896.7,2310.09 D5_3.2@2896.98,2309.82 D5_3.2@2900.91,2309.82 ; D5_3.2@2896.98,2309.82 2901.67,2305.12 2921.05,2305.12 2939.95,2286.23 2962.37,2286.23 U24_3.4@2963.49,2285.11
NetD5_4_2: D5_4.2 R193_4.1 U24_4.4 | length 125.5
  Top Layer w10: R193_4.1@1472.69,2367.84 1472.69,2319.48 D5_4.2@1472.96,2319.21 1502.68,2319.21 1524.51,2297.38 1536.61,2297.38 U24_4.4@1539.48,2294.51
NetD7_1: D7.1 R232.1 | length 102.4
  Top Layer w10: R232.1@3326.82,915.35 3400.28,915.35 3418.64,933.71 D7.1@3421.59,933.71
NetJ3_1: J3.1 R76.2 U8.7 | length 503
  Top Layer w10: U8.7@6233.73,563.22 6192.28,563.22 6179.83,575.67 6179.83,769.44 6214.19,803.8 J3.1@6313.42,803.8
  Bottom Layer w10: R76.2@6190.13,815.32 6276.23,815.32 J3.1@6287.74,803.8
NetJ3_2: J3.2 R76.1 U8.6 | length 661.4
  Top Layer w10: U8.6@6233.73,513.22 6194.73,513.22 6157.33,550.61 6157.33,813.03 6246.53,902.23 J3.2@6313.42,902.23
  Bottom Layer w10: R76.1@6190.13,862.57 6248.08,862.57 J3.2@6287.74,902.23
NetJ11_12: J11.12 R36.2 | length 365.7
  Top Layer w10: v2(5555.66,290.14) 5556.21,289.59 5556.21,206.84 J11.12@5556.77,206.28
  Bottom Layer w10: v2(5555.66,290.14) 5601.62,290.14 5625.95,314.47 5628.78,314.47 5690.88,376.57 5690.88,485.65 v2(5690,486.52)
NetJ11_15: J11.15 R37.1 | length 146.4
  Top Layer w10: J11.15@5493.78,340.14 R37.1@5493.78,486.52
NetJ11_18: J11.18 R38.1 | length 367.8
  Top Layer w10: J11.18@5462.28,206.29 5462.28,265.47 v2(5486.95,290.14)
  Bottom Layer w10: v2(5486.95,290.14) 5489.2,292.39 5512.95,292.39 5640,419.43 v2(5640,486.52)
NetJ11_21: J11.21 R39.1 | length 146.4
  Top Layer w10: J11.21@5399.29,340.14 R39.1@5399.29,486.52
NetJ11_25: J11.25 R40.1 | length 168.4
  Top Layer w10: R40.1@5308.43,481.52 5332.29,481.52 5338.15,475.66 5338.15,341.99 J11.25@5336.3,340.14
NetJ11_28: J11.28 R41.1 | length 438.1
  Top Layer w10: J11.28@5304.8,206.29 5304.8,244.95 5350,290.14 v2(5418.57,290.14)
  Bottom Layer w10: v2(5418.57,290.14) 5501.4,372.97 5501.4,373.53 5515.39,387.52 5515.95,387.52 5588.27,459.84 v2(5588.27,486.52)
NetJ11_31: J11.31 R42.1 | length 146.4
  Top Layer w10: J11.31@5241.81,340.14 R42.1@5241.81,486.52
NetJ11_33: J11.33 R43.1 | length 150.7
  Top Layer w10: R43.1@5200,486.52 5200,450.01 5210.32,439.69 J11.33@5210.32,340.14
NetJ11_37: J11.37 R44.1 | length 147.5
  Top Layer w10: J11.37@5147.32,340.14 5148.66,341.48 5148.66,485.18 R44.1@5150,486.52
NetJ11_39: J11.39 R45.1 | length 148.8
  Top Layer w10: R45.1@5110,486.52 5112.91,483.61 5112.91,343.06 J11.39@5115.83,340.14
NetJ11_45: J11.45 R46.1 | length 151.7
  Top Layer w10: J11.45@5021.34,340.14 5021.34,466.72 5036.34,481.72 R46.1@5036.34,485.66
NetJ11_49: J11.49 R47.2 | length 152.4
  Top Layer w10: J11.49@4958.35,340.14 4959.17,340.97 4959.17,465.89 4975,481.72 R47.2@4975,485.66
NetJ11_50: J11.50 R48.1 | length 395.1
  Top Layer w10: R48.1@4790,485.66 4790,348.41 4843.27,295.14 4921.78,295.14 4958.35,258.58 J11.50@4958.35,206.29
NetJ11_51: J11.51 R49.2 | length 149.6
  Top Layer w10: R49.2@4925,485.66 4930.85,479.8 4930.85,344.15 J11.51@4926.85,340.14
NetJ11_52: J11.52 R50.1 | length 402.4
  Top Layer w10: R50.1@4745,485.66 4745,365.14 4835,275.14 4916.5,275.14 4926.13,265.51 4926.13,207 J11.52@4926.85,206.29
NetJ11_53: J11.53 R51.2 | length 152.3
  Top Layer w10: R51.2@4878.86,485.66 4882.44,482.07 4882.44,454.91 4895.35,441.99 J11.53@4895.35,340.14
NetJ11_54: J11.54 R52.1 | length 712.8
  Top Layer w10: J11.54@4895.35,206.29 4895.45,206.39 4895.45,249.57 v2(4895.56,249.67)
  Int3 (Signal) w10: v2(4895.56,249.67) 4895.64,249.59 4994.59,249.59 5355.91,610.91 v2(5355.91,670.14)
NetJ11_55: J11.55 R53.2 | length 120.6
  Top Layer w10: R53.2@4835,485.66 4835,442.78 4863.86,413.92 J11.55@4863.86,377.03
NetJ11_56: J11.56 R54.1 | length 382.6
  Top Layer w10: v2(4850.09,249.67) 4851.27,249.67 4863.86,237.09 J11.56@4863.86,206.29
  Int3 (Signal) w10: v2(4614.73,485.04) v2(4850.09,249.67)
NetJ11_57: J11.57 R55.1 | length 149.6
  Top Layer w10: R55.1@4705.76,485.66 4706.07,485.34 4706.07,368.57 4711,363.64 4711,344.76 J11.57@4706.38,340.14
NetJ11_59: J11.59 R56.1 | length 151.7
  Top Layer w10: R56.1@4660,485.66 4660,451.86 4673.09,438.76 4673.09,391.25 4674.88,389.45 J11.59@4674.88,340.14
NetJ11_61: J11.61 R71.1 | length 678.1
  Top Layer w10: v2(4335.32,295.14) 4473.74,295.14 4478.56,290.32 4613.74,290.32 4638.54,315.13 4638.54,335.3 J11.61@4643.39,340.14
  Bottom Layer w10: v2@4160,486.15 4160,347.65 4212.51,295.14 v2(4335.32,295.14)
  other v2: 4160,486.52
NetJ11_68: J11.68 R58.1 | length 1755.1
  Top Layer w10: v2(4548.9,85.18) J11.68@4548.9,206.29
  Bottom Layer w8: v2(4548.9,85.18) 4653.12,189.41 5637.36,189.41 5758.03,310.09 5769.85,310.09 5926.08,466.31 5926.08,532.91 v2(5903.2,555.79)
NetJ11_69: J11.69 R59.2 | length 183.4
  Top Layer w10: J11.69@4517.4,340.14 4522.24,344.99 4522.24,435 4532.7,445.46 4562.45,445.46 4568.31,451.32 R59.2@4568.31,485.03
NetJ11_70: J11.70 R60.1 | length 1560.5
  Top Layer w8: J11.70@4517.4,206.29 v2(4517.4,249.67)
  Bottom Layer w8: v2(4517.4,249.67) 4541.35,249.67 4566.86,224.16 ; 5580.76,224.16 5584.78,224.16 5843.55,482.93
  Bottom Layer w10: 4566.86,224.16 5580.76,224.16 ; 5843.55,482.93 5876.41,515.79 v2(5903.2,515.79)
NetJ11_71: J11.71 R61.2 | length 162.5
  Top Layer w10: J11.71@4485.91,340.14 4490.75,344.99 4490.75,428.78 4523.27,461.3 4523.27,479.99 R61.2@4528.31,485.03
NetJ11_72: J11.72 R62.1 | length 1700.2
  Top Layer w10: v2(4485.91,85.18) J11.72@4485.91,206.29
  Bottom Layer w8: 5605.68,206.28 5875.18,475.79 v2(5903.2,475.79)
  Bottom Layer w10: v2(4485.91,85.18) 4607.01,206.28 5605.68,206.28
NetJ11_73: J11.73 R63.2 | length 158.9
  Top Layer w10: J11.73@4454.41,340.14 4459.25,344.99 4459.25,434.08 4482.95,457.78 4482.95,479.68 R63.2@4488.31,485.03
NetJ11_74: J11.74 R64.1 | length 1981
  Top Layer w10: v2(4454.41,85.18) J11.74@4454.41,206.29
  Bottom Layer w8: 5633.36,296.6 5634.77,296.6 5779.68,441.51 5779.68,442.92
  Bottom Layer w10: v2(4454.41,85.18) 4454.41,87.45 4476.02,109.06 4478.28,109.06 4485.91,116.68 4485.91,310.29 4491.76,316.14 5240.03,316.14 5312.2,243.98 5580.74,243.98 5633.36,296.6 ; 5779.68,442.92 5791.61,454.85 5791.61,491.28 v2(5903.2,602.87)
NetJ11_75: J11.75 R65.2 | length 155.4
  Top Layer w10: J11.75@4422.91,340.14 4422.91,443.44 4442.02,462.55 4442.02,478.75 R65.2@4448.31,485.03
NetJ11_77: J11.77 R194.2 | length 153.6
  Top Layer w10: J11.77@4391.42,340.14 4391.42,448.96 4405,462.54 R194.2@4405,488.13
NetJ11_79: J11.79 R66.2 | length 146.4
  Top Layer w10: J11.79@4359.92,340.14 R66.2@4359.92,486.52
NetJ11_81: J11.81 R67.2 | length 149.9
  Top Layer w10: R67.2@4320,486.52 4320,460.14 4328.43,451.72 J11.81@4328.43,340.14
NetJ11_85: J11.85 R68.2 | length 152.4
  Top Layer w10: J11.85@4265.43,340.14 4265.43,450.14 4280,464.71 R68.2@4280,486.52
NetJ11_87: J11.87 R69.2 | length 148.9
  Top Layer w10: J11.87@4233.94,340.14 4233.94,451.36 4240,457.43 R69.2@4240,486.52
NetJ11_99: J11.99 R72.2 | length 148.5
  Top Layer w10: J11.99@4044.96,340.14 4044.96,452.39 4050,457.43 R72.2@4050,486.52
NetJ11_101: J11.101 R73.2 | length 147.8
  Top Layer w10: R73.2@4010,486.52 4011.73,484.79 4011.73,341.88 J11.101@4013.46,340.14
NetJ11_103: J11.103 R74.2 | length 151.3
  Top Layer w10: R74.2@3970,486.52 3970,457.43 3981.97,445.46 J11.103@3981.97,340.14
NetJ11_105: J11.105 R75.2 | length 154.9
  Top Layer w10: R75.2@3930,486.52 3930,458.37 3950.47,437.9 J11.105@3950.47,340.14
NetJ11_107: J11.107 R195.2 | length 161.2
  Top Layer w10: R195.2@3881.08,485.66 3881.08,481.72 3918.98,443.82 J11.107@3918.98,340.14
NetJ11_108: J11.108 R196.1 | length 508.3
  Top Layer w10: R196.1@3785.24,485.66 3785.24,481.72 3755.52,452 3730.19,452 3707.28,429.1 3707.28,311.19 3729.6,288.88 3890.25,288.88 3916.68,262.45 3916.68,258.97 v2(3918.98,256.68) J11.108@3918.98,206.29
NetJ11_109: J11.109 R197.2 | length 169.6
  Top Layer w10: R197.2@3835,485.66 3835,481.72 3841.81,474.91 3845.75,474.91 3887.48,433.18 J11.109@3887.48,340.14
NetJ11_110: J11.110 R198.1 | length 486
  Top Layer w10: R198.1@3738.6,485.66 3714.49,485.66 3689.41,460.58 3689.41,303.79 3736.52,256.68 v2(3888.69,256.68) 3888.08,256.07 3888.08,206.89 J11.110@3887.48,206.29
NetQ1_1_4: Q1_1.4 R17_1.2 | length 780.1
  Int3 (Signal) w12: v2(4844,4527.49) 4901.35,4470.14 5395.81,4470.14 5491.26,4565.59 v2(5491.26,4635.15)
NetQ1_2_4: Q1_2.4 R17_2.2 | length 820.1
  Int3 (Signal) w10: v2(3416,4531.49) 3416,4504.14 3436.75,4483.4 4032.96,4483.4 4060.56,4511 v2(4060.56,4639.15)
NetQ1_3_4: Q1_3.4 R17_3.2 | length 846.9
  Int3 (Signal) w10: v2(1919.39,4543.1) 1919.39,4509.91 1955.17,4474.14 2527.67,4474.14 2566.65,4513.12 v2(2566.65,4648.6)
NetQ1_4_4: Q1_4.4 R17_4.2 | length 831.8
  Int3 (Signal) w10: v2(519,4554.43) 519,4516.31 533.91,4501.4 1131.26,4501.4 1166.38,4536.52 v2(1166.38,4662.09)
NetQ2_1_4: Q2_1.4 R18_1.1 | length 700.3
  Int3 (Signal) w12: v2(4994,4612.53) 4994,4661.07 5016.32,4683.4 5584.23,4683.4 5591.26,4676.37 v2(5591.26,4633.99)
NetQ2_2_4: Q2_2.4 R18_2.1 | length 642.5
  Int3 (Signal) w10: v2(3566,4616.53) 3631.37,4681.9 4119.35,4681.9 v2(4163.26,4637.99)
NetQ2_3_4: Q2_3.4 R18_3.1 | length 656.5
  Int3 (Signal) w10: v2(2069.39,4628.14) 2069.39,4648.66 2116.61,4695.87 2620.38,4695.87 v2(2666.65,4649.6)
NetQ2_4_4: Q2_4.4 R18_4.1 | length 690.8
  Int3 (Signal) w10: v2(669,4639.47) 669,4689.37 687.64,4708.02 1247.13,4708.02 1266.26,4688.88 v2(1266.26,4660.93)
NetQ3_1_4: Q3_1.4 R20_1.2 | length 383.9
  Int3 (Signal) w12: v2(5182.36,4526.49) 5182.36,4523.24 5193.13,4512.48 5193.13,4510.84 5208.98,4494.99 5386.69,4494.99 5443.39,4551.69 v2(5443.39,4635.15)
NetQ3_2_4: Q3_2.4 R20_2.2 | length 400.1
  Int3 (Signal) w10: v2(3754.36,4530.49) 3757,4527.85 3757,4511 3766.73,4501.27 3986.13,4501.27 4006.69,4521.83 v2(4006.69,4639.15)
NetQ3_3_4: Q3_3.4 R20_3.2 | length 446
  Int3 (Signal) w10: v2(2257.75,4542.1) 2257.75,4497.87 2263.61,4492.01 2490.87,4492.01 2514.01,4515.15 v2(2514.01,4648.6)
NetQ3_4_4: Q3_4.4 R20_4.2 | length 419.4
  Int3 (Signal) w10: v2(857.36,4553.43) 857.36,4530.17 868.26,4519.28 1097.59,4519.28 1118.39,4540.07 v2(1118.39,4662.09)
NetQ4_1_4: Q4_1.4 R21_1.1 | length 253.7
  Int3 (Signal) w12: v2(5332.36,4611.53) 5332.36,4634.24 5358.86,4660.74 5514.51,4660.74 v2(5541.26,4633.99)
NetQ4_2_4: Q4_2.4 R21_2.1 | length 239.8
  Int3 (Signal) w10: v2(3904.36,4615.53) 3952.86,4664.03 4087.23,4664.03 v2(4113.26,4637.99)
NetQ4_3_4: Q4_3.4 R21_3.1 | length 238
  Int3 (Signal) w10: v2(2407.75,4627.14) 2454.09,4673.48 2592.78,4673.48 v2(2616.65,4649.6)
NetQ4_4_4: Q4_4.4 R21_4.1 | length 270.5
  Int3 (Signal) w10: v2(1007.36,4638.47) 1007.36,4672.51 1025,4690.14 1201.03,4690.14 1214.16,4677.02 1214.16,4663.03 v2(1216.26,4660.93)
NetR1_1_2: R1_1.2 U1_1.3 | length 28.7
  Top Layer w10: U1_1.3@5339.02,2316.61 R1_1.2@5367.74,2316.61
NetR1_2_2: R1_2.2 U1_2.3 | length 38
  Top Layer w10: U1_2.3@3911.02,2320.61 3939.74,2320.61 R1_2.2@3946.33,2327.16
NetR1_3_2: R1_3.2 U1_3.3 | length 37.3
  Top Layer w10: U1_3.3@2414.42,2332.22 2414.49,2332.3 2444.9,2332.3 R1_3.2@2449.72,2337.12
NetR1_4_2: R1_4.2 U1_4.3 | length 28.7
  Top Layer w10: U1_4.3@990.4,2341.61 R1_4.2@1019.11,2341.61
NetR2_1_1: R2_1.1 R5_1.2 | length 124.3
  Top Layer w10: R2_1.1@5179.94,4148.06 5177.22,4145.34 5177.22,4090.92 5184.82,4083.32 5239.43,4083.32 R5_1.2@5239.91,4082.84
NetR2_1_2: R2_1.2 R4_1.2 | length 134.5
  Top Layer w10: R2_1.2@5179.94,3954.06 5179.94,4024.55 5189.01,4033.61 5239.14,4033.61 R4_1.2@5239.91,4032.84
NetR2_2_1: R2_2.1 R5_2.2 | length 124.3
  Top Layer w10: R2_2.1@3751.94,4152.06 3749.22,4149.34 3749.22,4094.92 3756.82,4087.32 3811.43,4087.32 R5_2.2@3811.91,4086.84
NetR2_2_2: R2_2.2 R4_2.2 | length 134.5
  Top Layer w10: R2_2.2@3751.94,3958.06 3751.94,4028.55 3761.01,4037.61 3811.14,4037.61 R4_2.2@3811.91,4036.84
NetR2_3_1: R2_3.1 R5_3.2 | length 124.3
  Top Layer w10: R2_3.1@2255.34,4163.67 2252.61,4160.94 2252.61,4106.52 2260.21,4098.93 2314.83,4098.93 R5_3.2@2315.31,4098.45
NetR2_3_2: R2_3.2 R4_3.2 | length 134.5
  Top Layer w10: R2_3.2@2255.34,3969.67 2255.34,4040.15 2264.4,4049.22 2314.53,4049.22 R4_3.2@2315.31,4048.45
NetR2_4_1: R2_4.1 R5_4.2 | length 124.3
  Top Layer w10: R2_4.1@831.32,4173.06 828.6,4170.34 828.6,4115.92 836.19,4108.32 890.81,4108.32 R5_4.2@891.29,4107.84
NetR2_4_2: R2_4.2 R4_4.2 | length 134.5
  Top Layer w10: R2_4.2@831.32,3979.06 831.32,4049.55 840.39,4058.61 890.52,4058.61 R4_4.2@891.29,4057.84
NetR9_1_2: R9_1.2 U2_1.3 | length 46.2
  Top Layer w10: U2_1.3@5623.26,2313.89 5623.34,2313.97 5664.24,2313.97 R9_1.2@5667.91,2317.64
NetR9_2_2: R9_2.2 U2_2.3 | length 46.2
  Top Layer w10: U2_2.3@4195.26,2317.89 4195.34,2317.97 4236.24,2317.97 R9_2.2@4239.91,2321.64
NetR9_3_2: R9_3.2 U2_3.3 | length 46.2
  Top Layer w10: U2_3.3@2698.65,2329.5 U2_3.3@2698.65,2329.5 2739.63,2329.58 R9_3.2@2743.31,2333.25
NetR9_4_2: R9_4.2 U2_4.3 | length 46.2
  Top Layer w10: U2_4.3@1274.64,2338.89 1274.72,2338.97 1315.62,2338.97 R9_4.2@1319.29,2342.64
NetR14_1_2: R14_1.2 U3_1.3 | length 50.5
  Top Layer w10: R14_1.2@5668.06,2766.46 5671,2763.52 U3_1.3@5671,2717.13
NetR14_2_2: R14_2.2 U3_2.3 | length 69.5
  Top Layer w10: R14_2.2@4242.8,2790.14 4242.31,2789.65 4242.31,2752.58 4243.08,2751.8 U3_2.3@4243.08,2721.13
NetR14_3_2: R14_3.2 U3_3.3 | length 57
  Top Layer w10: R14_3.2@2744.5,2780.14 2746.39,2778.26 2746.39,2724.03 U3_3.3@2746.47,2723.96
NetR14_4_2: R14_4.2 U3_4.3 | length 68.5
  Top Layer w10: R14_4.2@1321.84,2810.14 1321.55,2809.85 1321.55,2773.14 1322.46,2772.24 U3_4.3@1322.46,2742.13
